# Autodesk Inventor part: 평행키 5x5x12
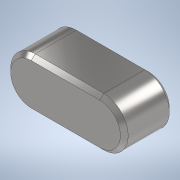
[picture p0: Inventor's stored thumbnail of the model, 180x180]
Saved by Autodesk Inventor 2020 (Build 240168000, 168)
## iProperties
Created: 2024-05
Part Number: 평행키 5x5x12
Material: 강철, 연강
Description: 키 및 해당 키홈
Document SubType Name: Modeling
Designer: oem
Density: 7.85 g/cm^3
Appearance: 기본값
Author: jhkim
Sending System: Autodesk Inventor 2025
Preprocessor: ST-DEVELOPER v20
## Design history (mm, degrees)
node "평행키 5x5x121"
node "솔리드1"
body "Solid1"
